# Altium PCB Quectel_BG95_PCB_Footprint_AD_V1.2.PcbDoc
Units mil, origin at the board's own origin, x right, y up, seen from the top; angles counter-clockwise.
Board outline 6000 x 4000 mil, 2 copper layers (Top Layer, Bottom Layer); 1 components, 0 nets, 102 pads, 0 vias.
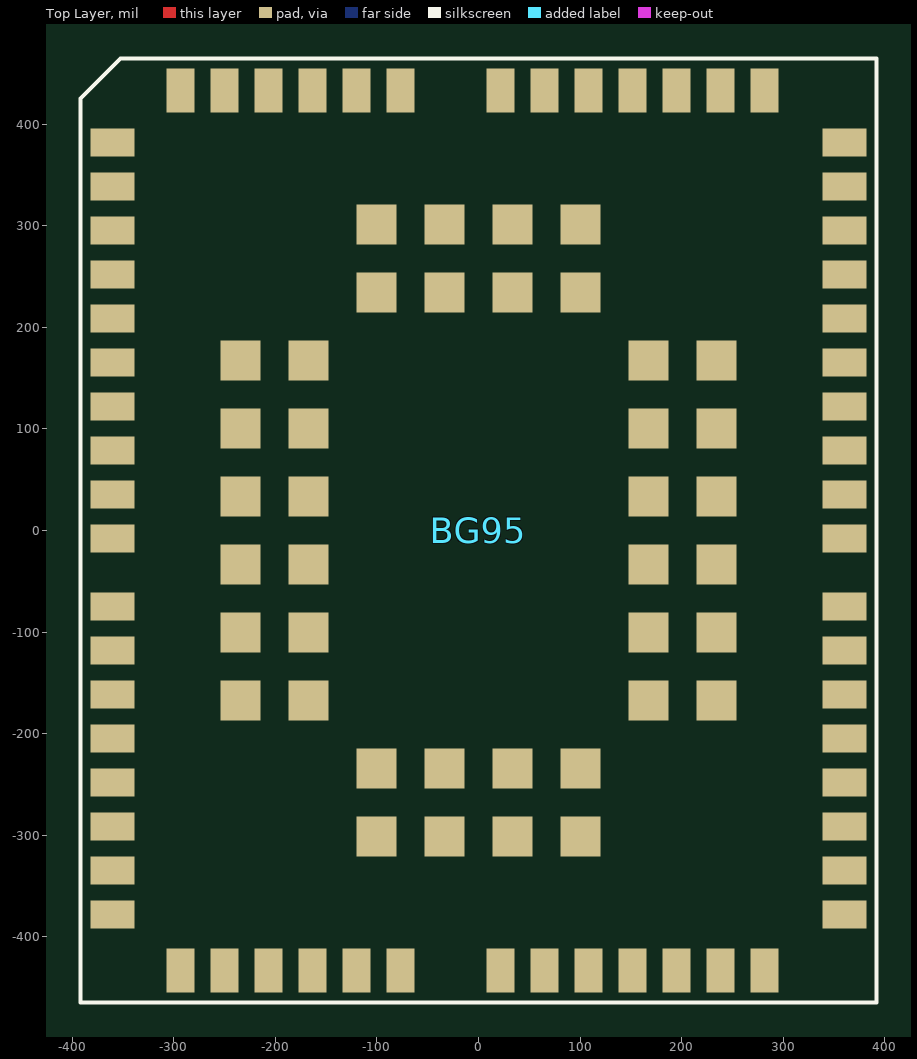
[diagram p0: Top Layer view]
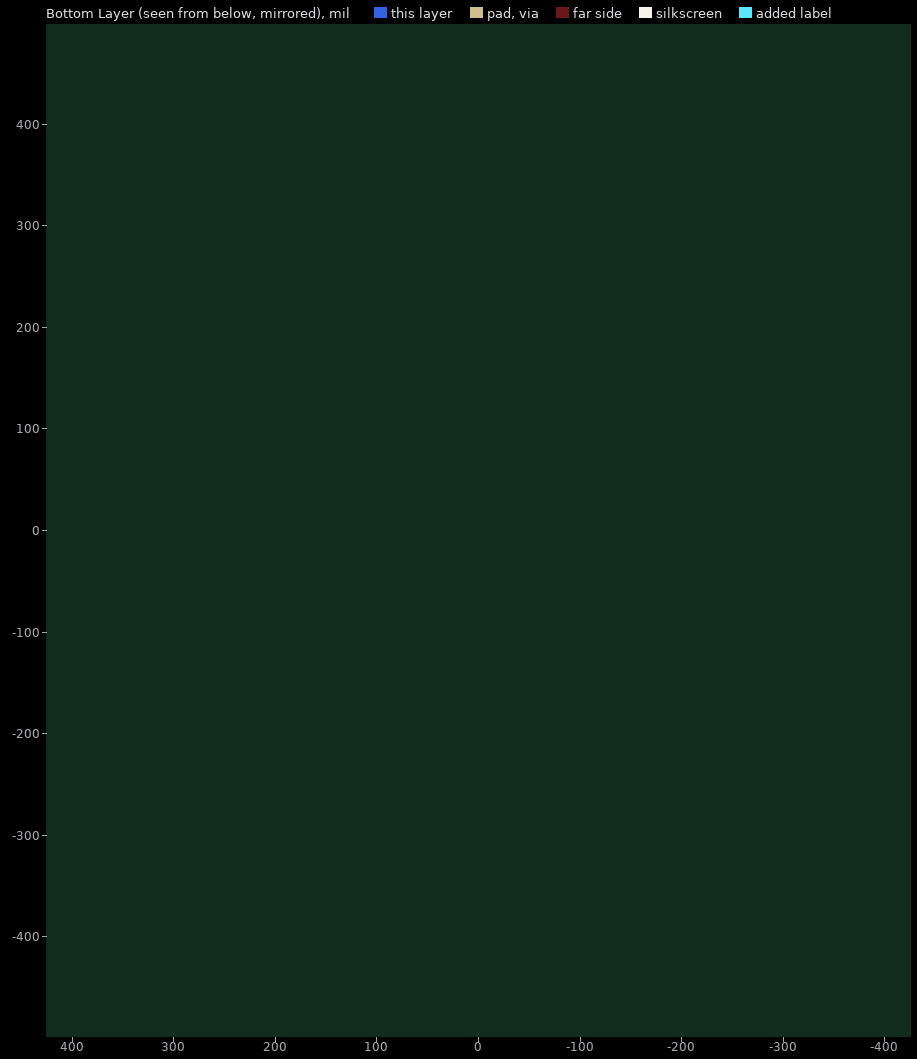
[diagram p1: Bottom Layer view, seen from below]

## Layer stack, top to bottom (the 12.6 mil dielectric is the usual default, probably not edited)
Top Layer: signal copper 1.4
Dielectric: dielectric 12.6, FR-4, Dk 4.8
Bottom Layer: signal copper 1.4

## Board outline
-2265,-2270 3735,-2270 3735,1730 -2265,1730

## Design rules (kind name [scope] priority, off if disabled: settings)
Clearance [All] p1: gap=10
PolygonConnect [All] p1: connectstyle=Relief reliefconductorwidth=10 reliefentries=4 polygonreliefangle="90 Angle" airgapwidth=10
RoutingVias [All] p1: holewidth=28 width=50 viastyle="Through Hole" minholewidth=28 minwidth=50 maxholewidth=28 maxwidth=50
SolderMaskExpansion [All] p1: expansion=4
Width [All] p1: maxlimit=10 minlimit=10 preferedwidth=10
28 further rules are at their usual default settings.

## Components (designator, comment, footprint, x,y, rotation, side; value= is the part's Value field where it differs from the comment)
BG95 "Comment" BG95 0,0 r0 top

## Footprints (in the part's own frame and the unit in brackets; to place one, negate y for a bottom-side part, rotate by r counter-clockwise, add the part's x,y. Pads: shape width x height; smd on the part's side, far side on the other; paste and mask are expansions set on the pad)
BG95 [mm]
  rect 1.1x0.7 smd mask+0.05: 1(-9.15,9.7) 2(-9.15,8.6) 3(-9.15,7.5) 4(-9.15,6.4) 5(-9.15,5.3) 6(-9.15,4.2) 7(-9.15,3.1) 8(-9.15,2) 9(-9.15,0.9) 10(-9.15,-0.2) 11(-9.15,-1.9) 12(-9.15,-3) 13(-9.15,-4.1) 14(-9.15,-5.2) 15(-9.15,-6.3) 16(-9.15,-7.4) 17(-9.15,-8.5) 18(-9.15,-9.6) 32(9.15,-9.6) 33(9.15,-8.5) 34(9.15,-7.4) 35(9.15,-6.3) 36(9.15,-5.2) 37(9.15,-4.1) 38(9.15,-3) 39(9.15,-1.9) 40(9.15,-0.2) 41(9.15,0.9) 42(9.15,2) 43(9.15,3.1) 44(9.15,4.2) 45(9.15,5.3) 46(9.15,6.4) 47(9.15,7.5) 48(9.15,8.6) 49(9.15,9.7)
  rect 0.7x1.1 smd mask+0.05: 19(-7.45,-11) 20(-6.35,-11) 21(-5.25,-11) 22(-4.15,-11) 23(-3.05,-11) 24(-1.95,-11) 25(0.55,-11) 26(1.65,-11) 27(2.75,-11) 28(3.85,-11) 29(4.95,-11) 30(6.05,-11) 31(7.15,-11) 50(7.15,11) 51(6.05,11) 52(4.95,11) 53(3.85,11) 54(2.75,11) 55(1.65,11) 56(0.55,11) 57(-1.95,11) 58(-3.05,11) 59(-4.15,11) 60(-5.25,11) 61(-6.35,11) 62(-7.45,11)
  rect 1x1 smd mask+0.05: 63(-5.95,4.25) 64(-5.95,2.55) 65(-5.95,0.85) 66(-5.95,-0.85) 67(-5.95,-2.55) 68(-5.95,-4.25) 69(-2.55,-7.65) 70(-0.85,-7.65) 71(0.85,-7.65) 72(2.55,-7.65) 73(5.95,-4.25) 74(5.95,-2.55) 75(5.95,-0.85) 76(5.95,0.85) 77(5.95,2.55) 78(5.95,4.25) 79(2.55,7.65) 80(0.85,7.65) 81(-0.85,7.65) 82(-2.55,7.65) 83(-4.25,4.25) 84(-4.25,2.55) 85(-4.25,0.85) 86(-4.25,-0.85) 87(-4.25,-2.55) 88(-4.25,-4.25) 89(-2.55,-5.95) 90(-0.85,-5.95) 91(0.85,-5.95) 92(2.55,-5.95) 93(4.25,-4.25) 94(4.25,-2.55) 95(4.25,-0.85) 96(4.25,0.85) 97(4.25,2.55) 98(4.25,4.25) 99(2.55,5.95) 100(0.85,5.95) 101(-0.85,5.95) 102(-2.55,5.95)
  silkscreen extent -9.95,-11.8 9.95,11.8

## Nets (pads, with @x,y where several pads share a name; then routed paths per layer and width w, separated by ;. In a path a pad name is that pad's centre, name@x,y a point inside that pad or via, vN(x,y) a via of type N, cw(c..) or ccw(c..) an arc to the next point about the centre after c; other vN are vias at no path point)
pads on no net: BG95.1 BG95.2 BG95.3 BG95.4 BG95.5 BG95.6 BG95.7 BG95.8 BG95.9 BG95.10 BG95.11 BG95.12 BG95.13 BG95.14 BG95.15 BG95.16 BG95.17 BG95.18 BG95.19 BG95.20 BG95.21 BG95.22 BG95.23 BG95.24 BG95.25 BG95.26 BG95.27 BG95.28 BG95.29 BG95.30 BG95.31 BG95.32 BG95.33 BG95.34 BG95.35 BG95.36 BG95.37 BG95.38 BG95.39 BG95.40 BG95.41 BG95.42 BG95.43 BG95.44 BG95.45 BG95.46 BG95.47 BG95.48 BG95.49 BG95.50 BG95.51 BG95.52 BG95.53 BG95.54 BG95.55 BG95.56 BG95.57 BG95.58 BG95.59 BG95.60 BG95.61 BG95.62 BG95.63 BG95.64 BG95.65 BG95.66 BG95.67 BG95.68 BG95.69 BG95.70 BG95.71 BG95.72 BG95.73 BG95.74 BG95.75 BG95.76 BG95.77 BG95.78 BG95.79 BG95.80 BG95.81 BG95.82 BG95.83 BG95.84 BG95.85 BG95.86 BG95.87 BG95.88 BG95.89 BG95.90 BG95.91 BG95.92 BG95.93 BG95.94 BG95.95 BG95.96 BG95.97 BG95.98 BG95.99 BG95.100 BG95.101 BG95.102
